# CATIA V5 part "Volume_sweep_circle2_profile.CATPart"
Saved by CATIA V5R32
Part number: Part1
Bounding box of the stored display mesh (mm): x -183.601 to 0, y -55 to 90.724, z -55 to 54.977
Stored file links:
  D:\PROJECTS\Project 2022\CATIA V5 6R 2022\Resources\Part Files\c17_catia_v6_6r2022_prt\Volume_sweep_circle2_profile.CATPart
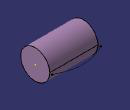
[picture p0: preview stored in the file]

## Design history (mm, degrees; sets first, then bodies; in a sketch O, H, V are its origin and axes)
Set1
  Sketch1 on xy-plane, origin (0, 0, 0), H (1, 0, 0), V (0, 1, 0)
    line L1 (0, 0) -> (-183.1008, 0)
    horizontal: L1 H
  Sketch2 on xy-plane, origin (0, 0, 0), H (1, 0, 0), V (0, 1, 0)
    spline S1 through (0, 65.5148) (-89.6654, 90.7245) (-183.6013, 65.5148)
    point P1 (0, 65.5148)
    coincidence: P1 V
  Sweep1: type Circle, Guide Sketch1, Reference Sketch2, Radius 55
Body1 (main body)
